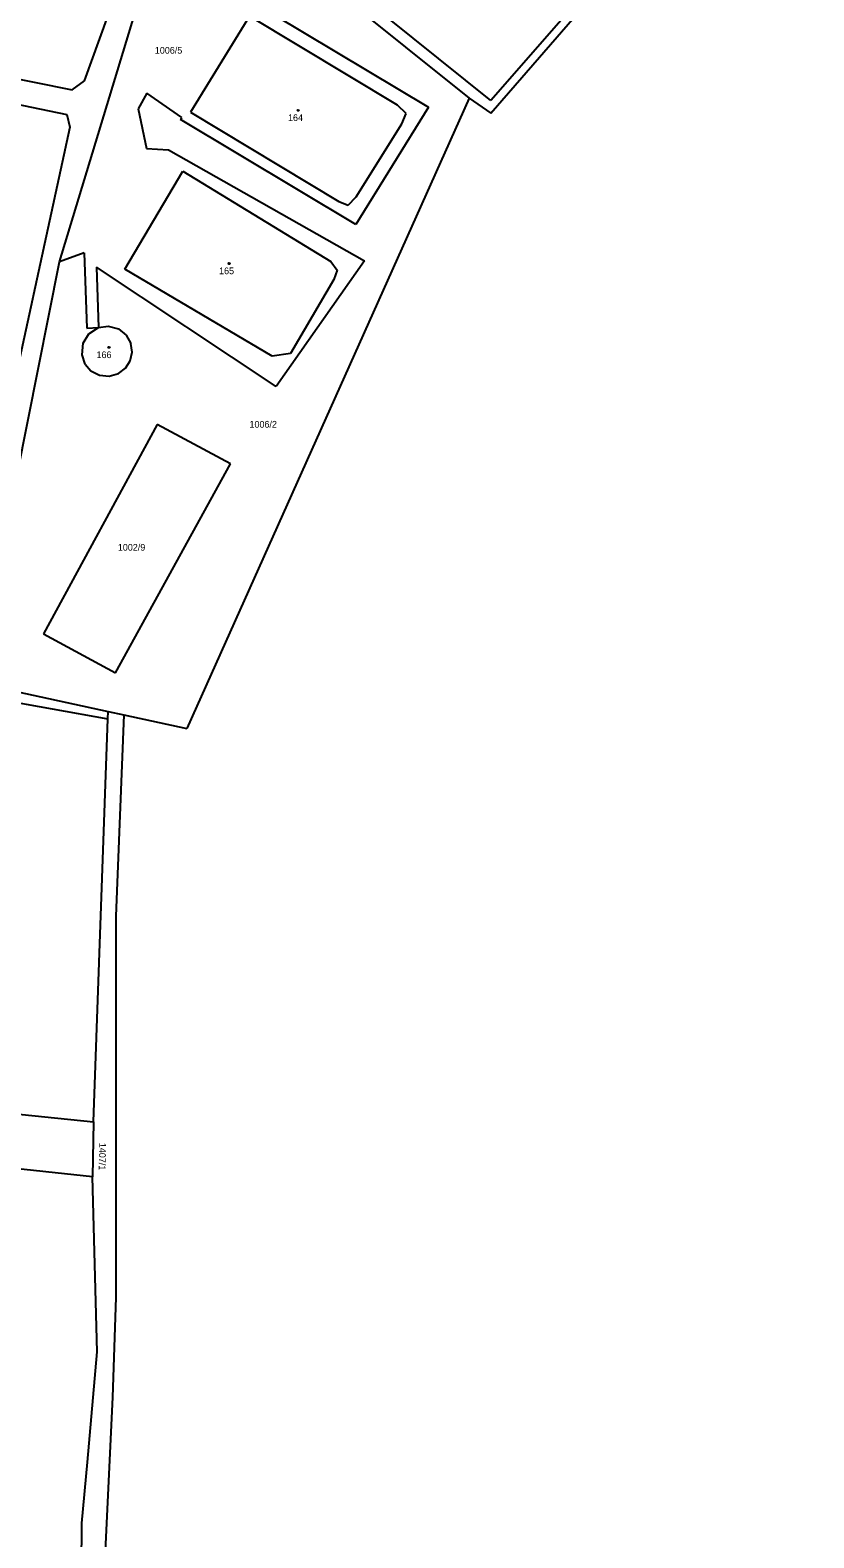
# Model space of a CAD drawing. Extents: x -852001 to -842497, y -1063614 to -1052182.
# Drawn here: x -849406 to -849207.6, y -1056881.4 to -1056500 of the extents above; entities that cross this region are included whole.
import ezdxf

# ---------------------------------------------------------------- set-up
doc = ezdxf.new("R2010")
doc.units = 0
for name, color, linetype in [('Default', 7, 'Continuous'), ('KN_HRANICE', 7, 'Continuous'), ('KN_KULTURY', 7, 'Continuous'), ('KN_PARCELY', 7, 'Continuous')]:
    doc.layers.add(name, color=color, linetype=linetype)

# ---------------------------------------------------------------- blocks, each defined once
blk = doc.blocks.new('402')
at = {"layer": 'Default'}
blk.add_lwpolyline([(0.09, 0.15), (0.18, 0), (0.09, -0.15), (-0.09, -0.15), (-0.18, 0), (-0.09, 0.15), (0.09, 0.15)], dxfattribs=at)

msp = doc.modelspace()

# ---------------------------------------------------------------- linework, layer by layer
at = {"layer": 'KN_HRANICE'}
for p, q in [((-849210.21, -1056427.21), (-849289.39, -1056517.79)), ((-849210.21, -1056427.21), (-849289.39, -1056517.79)), ((-849289.35, -1056520.97), (-849207.62, -1056426.96)), ((-849289.35, -1056520.97), (-849207.62, -1056426.96)), ((-849392.25, -1056512.84), (-849371.72, -1056456.31)), ((-849392.25, -1056512.84), (-849371.72, -1056456.31)), ((-849366.76, -1056459.53), (-849294.89, -1056517.18)), ((-849366.76, -1056459.53), (-849294.89, -1056517.18)), ((-849289.39, -1056517.79), (-849366.02, -1056456.29)), ((-849289.39, -1056517.79), (-849366.02, -1056456.29)), ((-849398.6, -1056558.62), (-849374.29, -1056478.85)), ((-849398.6, -1056558.62), (-849374.29, -1056478.85)), ((-849355.61, -1056489.31), (-849305.18, -1056519.49)), ((-849355.61, -1056489.31), (-849305.18, -1056519.49)), ((-849350.46, -1056496.46), (-849365.37, -1056520.72)), ((-849350.46, -1056496.46), (-849365.37, -1056520.72)), ((-849313.05, -1056518.99), (-849350.46, -1056496.46)), ((-849313.05, -1056518.99), (-849350.46, -1056496.46)), ((-849468.95, -1056500.27), (-849395.37, -1056515.06)), ((-849468.95, -1056500.27), (-849395.37, -1056515.06)), ((-849468.29, -1056506.44), (-849396.69, -1056521.32)), ((-849468.29, -1056506.44), (-849396.69, -1056521.32)), ((-849395.37, -1056515.06), (-849392.25, -1056512.84)), ((-849395.37, -1056515.06), (-849392.25, -1056512.84)), ((-849376.45, -1056515.96), (-849378.64, -1056519.87)), ((-849376.45, -1056515.96), (-849378.64, -1056519.87)), ((-849367.58, -1056522.09), (-849376.45, -1056515.96)), ((-849367.58, -1056522.09), (-849376.45, -1056515.96)), ((-849294.89, -1056517.18), (-849366.33, -1056676.64)), ((-849294.89, -1056517.18), (-849366.33, -1056676.64)), ((-849294.89, -1056517.18), (-849289.35, -1056520.97)), ((-849294.89, -1056517.18), (-849289.35, -1056520.97)), ((-849378.64, -1056519.87), (-849376.54, -1056529.98)), ((-849378.64, -1056519.87), (-849376.54, -1056529.98)), ((-849365.37, -1056520.72), (-849327.83, -1056543.32)), ((-849365.37, -1056520.72), (-849327.83, -1056543.32)), ((-849305.18, -1056519.49), (-849323.59, -1056549.16)), ((-849305.18, -1056519.49), (-849323.59, -1056549.16)), ((-849310.8, -1056521.11), (-849313.05, -1056518.99)), ((-849310.8, -1056521.11), (-849313.05, -1056518.99)), ((-849395.95, -1056524.56), (-849420.9, -1056639.14)), ((-849395.95, -1056524.56), (-849420.9, -1056639.14)), ((-849396.69, -1056521.32), (-849395.95, -1056524.56)), ((-849396.69, -1056521.32), (-849395.95, -1056524.56)), ((-849367.95, -1056522.58), (-849367.58, -1056522.09)), ((-849367.95, -1056522.58), (-849367.58, -1056522.09)), ((-849323.59, -1056549.16), (-849367.95, -1056522.58)), ((-849323.59, -1056549.16), (-849367.95, -1056522.58)), ((-849323.45, -1056542.2), (-849311.89, -1056523.66)), ((-849323.45, -1056542.2), (-849311.89, -1056523.66)), ((-849311.89, -1056523.66), (-849310.8, -1056521.11)), ((-849311.89, -1056523.66), (-849310.8, -1056521.11)), ((-849376.54, -1056529.98), (-849370.95, -1056530.31)), ((-849376.54, -1056529.98), (-849370.95, -1056530.31)), ((-849370.95, -1056530.31), (-849321.34, -1056558.37)), ((-849370.95, -1056530.31), (-849321.34, -1056558.37)), ((-849382.03, -1056560.46), (-849367.31, -1056535.71)), ((-849382.03, -1056560.46), (-849367.31, -1056535.71)), ((-849367.31, -1056535.71), (-849329.91, -1056558.5)), ((-849367.31, -1056535.71), (-849329.91, -1056558.5)), ((-849327.83, -1056543.32), (-849325.52, -1056544.25)), ((-849327.83, -1056543.32), (-849325.52, -1056544.25)), ((-849325.52, -1056544.25), (-849323.45, -1056542.2)), ((-849325.52, -1056544.25), (-849323.45, -1056542.2)), ((-849414.91, -1056640.62), (-849398.6, -1056558.62)), ((-849414.91, -1056640.62), (-849398.6, -1056558.62)), ((-849392.34, -1056556.32), (-849398.6, -1056558.62)), ((-849392.34, -1056556.32), (-849398.6, -1056558.62)), ((-849392.34, -1056556.32), (-849391.63, -1056575.35)), ((-849392.34, -1056556.32), (-849391.63, -1056575.35)), ((-849321.34, -1056558.37), (-849343.7, -1056590.17)), ((-849321.34, -1056558.37), (-849343.7, -1056590.17)), ((-849329.91, -1056558.5), (-849328.28, -1056560.68)), ((-849329.91, -1056558.5), (-849328.28, -1056560.68)), ((-849343.7, -1056590.17), (-849389.23, -1056559.95)), ((-849389.23, -1056559.95), (-849388.71, -1056575.25)), ((-849343.7, -1056590.17), (-849389.23, -1056559.95)), ((-849389.23, -1056559.95), (-849388.71, -1056575.25)), ((-849344.74, -1056582.45), (-849382.03, -1056560.46)), ((-849344.74, -1056582.45), (-849382.03, -1056560.46)), ((-849328.28, -1056560.68), (-849329.1, -1056563.12)), ((-849328.28, -1056560.68), (-849329.1, -1056563.12)), ((-849329.1, -1056563.12), (-849340.13, -1056581.78)), ((-849329.1, -1056563.12), (-849340.13, -1056581.78)), ((-849392.59, -1056579.22), (-849391.16, -1056576.85)), ((-849392.59, -1056579.22), (-849391.16, -1056576.85)), ((-849391.63, -1056575.35), (-849388.71, -1056575.25)), ((-849391.63, -1056575.35), (-849388.71, -1056575.25)), ((-849391.16, -1056576.85), (-849388.71, -1056575.25)), ((-849391.16, -1056576.85), (-849388.71, -1056575.25)), ((-849388.71, -1056575.25), (-849386.26, -1056574.88)), ((-849388.71, -1056575.25), (-849386.26, -1056574.88)), ((-849386.26, -1056574.88), (-849383.61, -1056575.59)), ((-849386.26, -1056574.88), (-849383.61, -1056575.59)), ((-849383.61, -1056575.59), (-849381.66, -1056577.17)), ((-849383.61, -1056575.59), (-849381.66, -1056577.17)), ((-849381.66, -1056577.17), (-849380.5, -1056579.27)), ((-849381.66, -1056577.17), (-849380.5, -1056579.27)), ((-849392.85, -1056582.1), (-849392.59, -1056579.22)), ((-849392.85, -1056582.1), (-849392.59, -1056579.22)), ((-849392.03, -1056584.47), (-849392.85, -1056582.1)), ((-849392.03, -1056584.47), (-849392.85, -1056582.1)), ((-849380.66, -1056583.65), (-849380.19, -1056581.45)), ((-849380.66, -1056583.65), (-849380.19, -1056581.45)), ((-849380.19, -1056581.45), (-849380.5, -1056579.27)), ((-849380.19, -1056581.45), (-849380.5, -1056579.27)), ((-849340.13, -1056581.78), (-849344.74, -1056582.45)), ((-849340.13, -1056581.78), (-849344.74, -1056582.45)), ((-849392.03, -1056584.47), (-849390.61, -1056586.14)), ((-849392.03, -1056584.47), (-849390.61, -1056586.14)), ((-849383.61, -1056586.88), (-849381.83, -1056585.5)), ((-849383.61, -1056586.88), (-849381.83, -1056585.5)), ((-849381.83, -1056585.5), (-849380.66, -1056583.65)), ((-849381.83, -1056585.5), (-849380.66, -1056583.65)), ((-849390.61, -1056586.14), (-849388.43, -1056587.31)), ((-849390.61, -1056586.14), (-849388.43, -1056587.31)), ((-849388.43, -1056587.31), (-849385.96, -1056587.57)), ((-849388.43, -1056587.31), (-849385.96, -1056587.57)), ((-849385.96, -1056587.57), (-849383.61, -1056586.88)), ((-849385.96, -1056587.57), (-849383.61, -1056586.88)), ((-849373.81, -1056599.77), (-849402.6, -1056652.68)), ((-849373.81, -1056599.77), (-849402.6, -1056652.68)), ((-849355.26, -1056609.68), (-849373.81, -1056599.77)), ((-849355.26, -1056609.68), (-849373.81, -1056599.77)), ((-849384.36, -1056662.54), (-849355.26, -1056609.68)), ((-849384.36, -1056662.54), (-849355.26, -1056609.68)), ((-849402.6, -1056652.68), (-849384.36, -1056662.54)), ((-849402.6, -1056652.68), (-849384.36, -1056662.54)), ((-849495.08, -1056654.69), (-849386.31, -1056674.19)), ((-849495.08, -1056654.69), (-849386.31, -1056674.19)), ((-849413.8, -1056666.37), (-849386.24, -1056672.33)), ((-849413.8, -1056666.37), (-849386.24, -1056672.33)), ((-849386.31, -1056674.19), (-849386.24, -1056672.33)), ((-849386.31, -1056674.19), (-849386.24, -1056672.33)), ((-849386.24, -1056672.33), (-849382.3, -1056673.18)), ((-849386.24, -1056672.33), (-849382.3, -1056673.18)), ((-849382.3, -1056673.18), (-849384.29, -1056724.14)), ((-849382.3, -1056673.18), (-849384.29, -1056724.14)), ((-849382.3, -1056673.18), (-849366.33, -1056676.64)), ((-849382.3, -1056673.18), (-849366.33, -1056676.64)), ((-849389.98, -1056776.11), (-849386.31, -1056674.19)), ((-849389.98, -1056776.11), (-849386.31, -1056674.19)), ((-849384.29, -1056724.14), (-849384.29, -1056820.56)), ((-849384.29, -1056724.14), (-849384.29, -1056820.56)), ((-849445.01, -1056770.52), (-849389.98, -1056776.11)), ((-849445.01, -1056770.52), (-849389.98, -1056776.11)), ((-849389.98, -1056776.11), (-849390.25, -1056790.03)), ((-849389.98, -1056776.11), (-849390.25, -1056790.03)), ((-849390.25, -1056790.03), (-849491.12, -1056779.44)), ((-849390.25, -1056790.03), (-849491.12, -1056779.44)), ((-849389.06, -1056834.36), (-849390.25, -1056790.03)), ((-849389.06, -1056834.36), (-849390.25, -1056790.03)), ((-849384.29, -1056820.56), (-849385.12, -1056845.77)), ((-849384.29, -1056820.56), (-849385.12, -1056845.77)), ((-849391.44, -1056862.27), (-849389.06, -1056834.36)), ((-849391.44, -1056862.27), (-849389.06, -1056834.36)), ((-849385.12, -1056845.77), (-849387.47, -1056894.86)), ((-849385.12, -1056845.77), (-849387.47, -1056894.86)), ((-849392.9, -1056877.65), (-849391.44, -1056862.27)), ((-849392.9, -1056877.65), (-849391.44, -1056862.27)), ((-849393.03, -1056888.92), (-849392.9, -1056877.65)), ((-849393.03, -1056888.92), (-849392.9, -1056877.65))]:
    msp.add_line(p, q, dxfattribs=at)

# ---------------------------------------------------------------- block references
at = {"layer": 'KN_KULTURY'}
for p in [(-849338.14, -1056520.29), (-849338.14, -1056520.29), (-849355.62, -1056559.04), (-849355.62, -1056559.04), (-849386.03, -1056580.22), (-849386.03, -1056580.22)]:
    msp.add_blockref('402', p, dxfattribs=at)

# ---------------------------------------------------------------- texts
at = {"layer": 'KN_PARCELY'}
for s, p in [('1006/5', (-849374.44, -1056505.96)), ('1006/5', (-849374.44, -1056505.96)), ('164', (-849340.73, -1056522.99)), ('164', (-849340.73, -1056522.99)), ('165', (-849358.17, -1056561.74)), ('165', (-849358.17, -1056561.74)), ('166', (-849389.19, -1056582.97)), ('166', (-849389.19, -1056582.97)), ('1006/2', (-849350.48, -1056600.55)), ('1006/2', (-849350.48, -1056600.55)), ('1002/9', (-849383.8, -1056631.68)), ('1002/9', (-849383.8, -1056631.68))]:
    msp.add_text(s, height=1.7, dxfattribs=at).set_placement(p)
msp.add_text('1407/1', height=1.7, rotation=268.775, dxfattribs=at).set_placement((-849388.48, -1056781.44))
msp.add_text('1407/1', height=1.7, rotation=268.775, dxfattribs=at).set_placement((-849388.48, -1056781.44))

doc.saveas('drawing.dxf')
